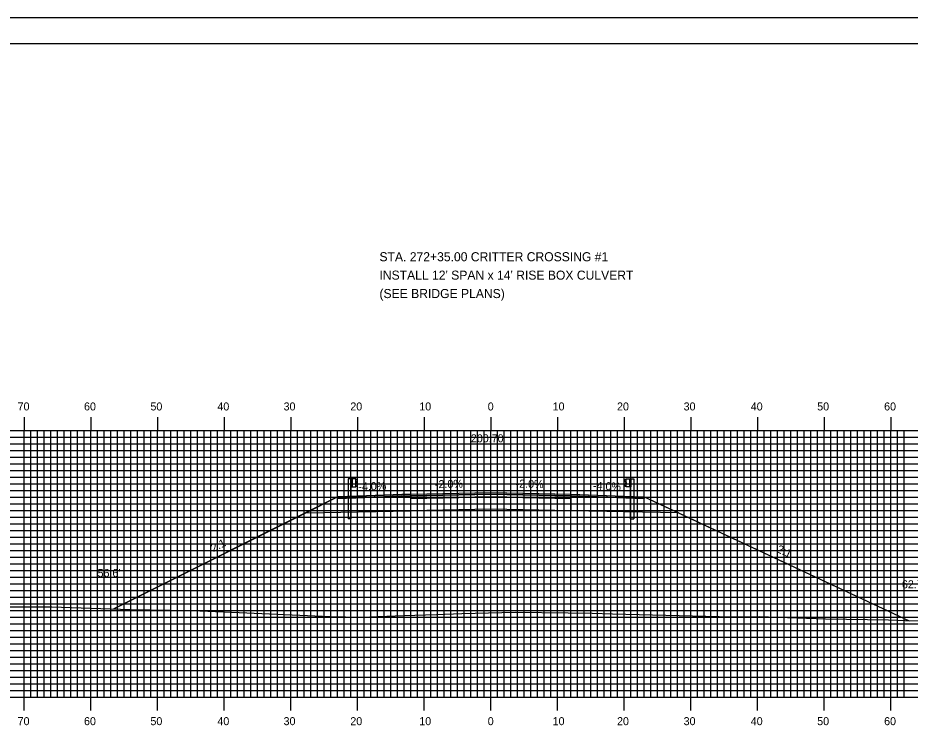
# Model space of a CAD drawing. Extents: x 1808619 to 1808962, y 442591 to 442811.
# Drawn here: x 1808713.9 to 1808847.7, y 442702.5 to 442810.5 of the extents above; entities that cross this region are included whole.
import ezdxf

# ---------------------------------------------------------------- set-up
doc = ezdxf.new("R2010")
doc.units = 0
for name, color, linetype in [('ANNOTATION', 7, 'Continuous'), ('BORDER', 7, 'Continuous'), ('D_Guardrail_Beam_Lt', 7, 'Continuous'), ('D_Guardrail_Beam_Rt', 7, 'Continuous'), ('D_Roadway_Centerline', 7, 'Continuous'), ('D_Roadway_Centerline_Text', 7, 'Continuous'), ('D_Roadway_Edge_Shoulder', 7, 'Continuous'), ('D_Roadway_Edge_TW', 7, 'Continuous'), ('D_Roadway_Pavement', 7, 'Continuous'), ('D_Roadway_SlopeLines', 7, 'Continuous'), ('D_Roadway_SubGrade', 7, 'Continuous'), ('D_Text_Standard', 7, 'Continuous'), ('H_V ANNOTATION', 7, 'Continuous'), ('MAJOR', 7, 'Continuous'), ('MINOR', 7, 'Continuous'), ('PLOT BOUNDARY', 7, 'Continuous'), ('S_Roadway_Centerline', 7, 'Continuous')]:
    doc.layers.add(name, color=color, linetype=linetype)

msp = doc.modelspace()

# ---------------------------------------------------------------- linework, layer by layer
at = {"layer": 'BORDER'}
msp.add_lwpolyline([(1808635.21, 442596.67), (1808955.21, 442596.67), (1808955.21, 442806.67), (1808635.21, 442806.67)], close=True, dxfattribs=at)
at = {"layer": 'D_Guardrail_Beam_Lt'}
for p, q in [((1808763.38, 442741.39), (1808763.38, 442735.39)), ((1808763.85, 442741.39), (1808763.38, 442741.39)), ((1808764.54, 442741.39), (1808763.85, 442741.39)), ((1808763.85, 442741.39), (1808763.85, 442740.23)), ((1808763.92, 442741.39), (1808763.92, 442740.23)), ((1808764.02, 442741.39), (1808764.02, 442740.23)), ((1808764.54, 442740.23), (1808764.54, 442741.39)), ((1808764.54, 442741.31), (1808764.61, 442741.3)), ((1808764.54, 442740.85), (1808764.54, 442740.78)), ((1808764.77, 442741.05), (1808764.58, 442740.91)), ((1808764.58, 442740.71), (1808764.77, 442740.57)), ((1808764.63, 442741.29), (1808764.77, 442741.19)), ((1808764.77, 442740.43), (1808764.63, 442740.33)), ((1808763.85, 442740.23), (1808764.54, 442740.23)), ((1808763.87, 442735.39), (1808763.87, 442740.23)), ((1808764.61, 442740.32), (1808764.54, 442740.31)), ((1808763.87, 442735.39), (1808763.38, 442735.39))]:
    msp.add_line(p, q, dxfattribs=at)
for centre, major_axis, start_param, end_param in [((1808764.62, 442740.85), (-0.0789, 0), 5.323254, 6.283185), ((1808764.62, 442740.78), (-0.0789, 0), 6.283185, 7.243116), ((1808764.61, 442741.25), (0.0417, 0), 0.959931, 1.376053), ((1808764.72, 442741.12), (0.0877, 0), 5.323254, 7.243116), ((1808764.72, 442740.5), (0.0877, 0), 5.323254, 7.243116), ((1808764.61, 442740.37), (0.0417, 0), 4.907132, 5.323254)]:
    msp.add_ellipse(centre, major_axis=major_axis, ratio=0.995501, start_param=start_param, end_param=end_param, dxfattribs=at)
at = {"layer": 'D_Guardrail_Beam_Rt'}
for p, q in [((1808804.99, 442741.29), (1808804.85, 442741.19)), ((1808804.85, 442741.05), (1808805.04, 442740.91)), ((1808805.04, 442740.71), (1808804.85, 442740.57)), ((1808804.85, 442740.43), (1808804.99, 442740.33)), ((1808805.08, 442741.31), (1808805.01, 442741.3)), ((1808805.08, 442741.39), (1808805.77, 442741.39)), ((1808805.08, 442740.23), (1808805.08, 442741.39)), ((1808805.08, 442740.85), (1808805.08, 442740.78)), ((1808805.6, 442741.39), (1808805.6, 442740.23)), ((1808805.71, 442741.39), (1808805.71, 442740.23)), ((1808805.77, 442741.39), (1808806.24, 442741.39)), ((1808805.77, 442741.39), (1808805.77, 442740.23)), ((1808806.24, 442741.39), (1808806.24, 442735.39)), ((1808805.01, 442740.32), (1808805.08, 442740.31)), ((1808805.77, 442740.23), (1808805.08, 442740.23)), ((1808805.75, 442735.39), (1808805.75, 442740.23)), ((1808805.75, 442735.39), (1808806.24, 442735.39))]:
    msp.add_line(p, q, dxfattribs=at)
for centre, major_axis, start_param, end_param in [((1808804.9, 442741.12), (-0.0877, 0), 5.323254, 7.243116), ((1808804.9, 442740.5), (-0.0877, 0), 5.323254, 7.243116), ((1808805.02, 442741.25), (-0.0417, 0), 4.907132, 5.323254), ((1808805, 442740.85), (0.0789, 0), 0, 0.959931), ((1808805, 442740.78), (0.0789, 0), 5.323254, 6.283185), ((1808805.02, 442740.37), (-0.0417, 0), 0.959931, 1.376053)]:
    msp.add_ellipse(centre, major_axis=major_axis, ratio=0.995501, start_param=start_param, end_param=end_param, dxfattribs=at)
at = {"layer": 'D_Roadway_Centerline'}
msp.add_lwpolyline([(1808728.25, 442721.91), (1808757.06, 442736.32), (1808761.81, 442738.69), (1808764.81, 442738.81), (1808772.81, 442739.13), (1808784.81, 442739.37), (1808796.81, 442739.13), (1808804.81, 442738.81), (1808807.81, 442738.69), (1808812.92, 442736.31), (1808847.56, 442720.14)], dxfattribs=at)
at = {"layer": 'D_Roadway_Edge_Shoulder'}
for points in [[(1808772.81, 442739.13), (1808764.81, 442738.81), (1808764.81, 442738.81), (1808761.81, 442738.69), (1808761.81, 442738.44), (1808772.81, 442738.88)], [(1808796.81, 442739.13), (1808804.81, 442738.81), (1808804.81, 442738.81), (1808807.81, 442738.69), (1808807.81, 442738.44), (1808796.81, 442738.88)]]:
    msp.add_lwpolyline(points, close=True, dxfattribs=at)
at = {"layer": 'D_Roadway_Edge_TW'}
msp.add_lwpolyline([(1808772.81, 442738.88), (1808772.81, 442739.13), (1808784.81, 442739.37), (1808796.81, 442739.13), (1808796.81, 442738.88), (1808784.81, 442739.12)], close=True, dxfattribs=at)
at = {"layer": 'D_Roadway_Pavement'}
msp.add_lwpolyline([(1808772.81, 442738.46), (1808772.81, 442738.88), (1808784.81, 442739.12), (1808796.81, 442738.88), (1808796.81, 442738.46), (1808784.81, 442738.7)], close=True, dxfattribs=at)
for points in [[(1808772.81, 442738.88), (1808772.81, 442738.46)], [(1808796.81, 442738.88), (1808796.81, 442738.46)]]:
    msp.add_lwpolyline(points, dxfattribs=at)
at = {"layer": 'D_Roadway_SlopeLines'}
for points in [[(1808761.81, 442738.69), (1808728.25, 442721.91)], [(1808807.81, 442738.69), (1808847.56, 442720.14)]]:
    msp.add_lwpolyline(points, dxfattribs=at)
at = {"layer": 'D_Roadway_SubGrade'}
for points in [[(1808772.81, 442738.46), (1808772.81, 442738.88), (1808761.81, 442738.44), (1808761.81, 442738.69), (1808757.06, 442736.32), (1808772.81, 442736.63)], [(1808772.81, 442736.63), (1808772.81, 442738.88), (1808772.81, 442738.46), (1808784.81, 442738.7), (1808796.81, 442738.46), (1808796.81, 442738.88), (1808796.81, 442736.63), (1808784.81, 442736.87)], [(1808796.81, 442738.46), (1808796.81, 442738.88), (1808807.81, 442738.44), (1808807.81, 442738.69), (1808812.92, 442736.31), (1808796.81, 442736.63)]]:
    msp.add_lwpolyline(points, close=True, dxfattribs=at)
at = {"layer": 'MAJOR'}
for p, q in [((1808714.81, 442750.67), (1808714.81, 442748.67)), ((1808724.81, 442750.67), (1808724.81, 442748.67)), ((1808734.81, 442750.67), (1808734.81, 442748.67)), ((1808744.81, 442750.67), (1808744.81, 442748.67)), ((1808754.81, 442750.67), (1808754.81, 442748.67)), ((1808764.81, 442750.67), (1808764.81, 442748.67)), ((1808774.81, 442750.67), (1808774.81, 442748.67)), ((1808784.81, 442750.67), (1808784.81, 442748.67)), ((1808794.81, 442750.67), (1808794.81, 442748.67)), ((1808804.81, 442750.67), (1808804.81, 442748.67)), ((1808814.81, 442750.67), (1808814.81, 442748.67)), ((1808824.81, 442750.67), (1808824.81, 442748.67)), ((1808834.81, 442750.67), (1808834.81, 442748.67)), ((1808844.81, 442750.67), (1808844.81, 442748.67)), ((1808644.81, 442748.67), (1808924.81, 442748.67)), ((1808644.81, 442748.67), (1808924.81, 442748.67)), ((1808714.81, 442708.67), (1808714.81, 442748.67)), ((1808724.81, 442708.67), (1808724.81, 442748.67)), ((1808734.81, 442708.67), (1808734.81, 442748.67)), ((1808744.81, 442708.67), (1808744.81, 442748.67)), ((1808754.81, 442708.67), (1808754.81, 442748.67)), ((1808764.81, 442708.67), (1808764.81, 442748.67)), ((1808774.81, 442708.67), (1808774.81, 442748.67)), ((1808784.81, 442708.67), (1808784.81, 442748.67)), ((1808794.81, 442708.67), (1808794.81, 442748.67)), ((1808804.81, 442708.67), (1808804.81, 442748.67)), ((1808814.81, 442708.67), (1808814.81, 442748.67)), ((1808824.81, 442708.67), (1808824.81, 442748.67)), ((1808834.81, 442708.67), (1808834.81, 442748.67)), ((1808844.81, 442708.67), (1808844.81, 442748.67)), ((1808644.81, 442743.67), (1808924.81, 442743.67)), ((1808644.81, 442738.67), (1808924.81, 442738.67)), ((1808644.81, 442733.67), (1808924.81, 442733.67)), ((1808644.81, 442728.67), (1808924.81, 442728.67)), ((1808644.81, 442723.67), (1808924.81, 442723.67)), ((1808644.81, 442718.67), (1808924.81, 442718.67)), ((1808644.81, 442713.67), (1808924.81, 442713.67)), ((1808644.81, 442708.67), (1808924.81, 442708.67)), ((1808644.81, 442708.67), (1808924.81, 442708.67)), ((1808714.81, 442706.66), (1808714.81, 442708.67)), ((1808724.81, 442706.66), (1808724.81, 442708.67)), ((1808734.81, 442706.66), (1808734.81, 442708.67)), ((1808744.81, 442706.66), (1808744.81, 442708.67)), ((1808754.81, 442706.66), (1808754.81, 442708.67)), ((1808764.81, 442706.66), (1808764.81, 442708.67)), ((1808774.81, 442706.66), (1808774.81, 442708.67)), ((1808784.81, 442706.66), (1808784.81, 442708.67)), ((1808794.81, 442706.66), (1808794.81, 442708.67)), ((1808804.81, 442706.66), (1808804.81, 442708.67)), ((1808814.81, 442706.66), (1808814.81, 442708.67)), ((1808824.81, 442706.66), (1808824.81, 442708.67)), ((1808834.81, 442706.66), (1808834.81, 442708.67)), ((1808844.81, 442706.66), (1808844.81, 442708.67))]:
    msp.add_line(p, q, dxfattribs=at)
at = {"layer": 'MINOR'}
for p, q in [((1808715.81, 442708.67), (1808715.81, 442748.67)), ((1808716.81, 442708.67), (1808716.81, 442748.67)), ((1808717.81, 442708.67), (1808717.81, 442748.67)), ((1808718.81, 442708.67), (1808718.81, 442748.67)), ((1808719.81, 442708.67), (1808719.81, 442748.67)), ((1808720.81, 442708.67), (1808720.81, 442748.67)), ((1808721.81, 442708.67), (1808721.81, 442748.67)), ((1808722.81, 442708.67), (1808722.81, 442748.67)), ((1808723.81, 442708.67), (1808723.81, 442748.67)), ((1808725.81, 442708.67), (1808725.81, 442748.67)), ((1808726.81, 442708.67), (1808726.81, 442748.67)), ((1808727.81, 442708.67), (1808727.81, 442748.67)), ((1808728.81, 442708.67), (1808728.81, 442748.67)), ((1808729.81, 442708.67), (1808729.81, 442748.67)), ((1808730.81, 442708.67), (1808730.81, 442748.67)), ((1808731.81, 442708.67), (1808731.81, 442748.67)), ((1808732.81, 442708.67), (1808732.81, 442748.67)), ((1808733.81, 442708.67), (1808733.81, 442748.67)), ((1808735.81, 442708.67), (1808735.81, 442748.67)), ((1808736.81, 442708.67), (1808736.81, 442748.67)), ((1808737.81, 442708.67), (1808737.81, 442748.67)), ((1808738.81, 442708.67), (1808738.81, 442748.67)), ((1808739.81, 442708.67), (1808739.81, 442748.67)), ((1808740.81, 442708.67), (1808740.81, 442748.67)), ((1808741.81, 442708.67), (1808741.81, 442748.67)), ((1808742.81, 442708.67), (1808742.81, 442748.67)), ((1808743.81, 442708.67), (1808743.81, 442748.67)), ((1808745.81, 442708.67), (1808745.81, 442748.67)), ((1808746.81, 442708.67), (1808746.81, 442748.67)), ((1808747.81, 442708.67), (1808747.81, 442748.67)), ((1808748.81, 442708.67), (1808748.81, 442748.67)), ((1808749.81, 442708.67), (1808749.81, 442748.67)), ((1808750.81, 442708.67), (1808750.81, 442748.67)), ((1808751.81, 442708.67), (1808751.81, 442748.67)), ((1808752.81, 442708.67), (1808752.81, 442748.67)), ((1808753.81, 442708.67), (1808753.81, 442748.67)), ((1808755.81, 442708.67), (1808755.81, 442748.67)), ((1808756.81, 442708.67), (1808756.81, 442748.67)), ((1808757.81, 442708.67), (1808757.81, 442748.67)), ((1808758.81, 442708.67), (1808758.81, 442748.67)), ((1808759.81, 442708.67), (1808759.81, 442748.67)), ((1808760.81, 442708.67), (1808760.81, 442748.67)), ((1808761.81, 442708.67), (1808761.81, 442748.67)), ((1808762.81, 442708.67), (1808762.81, 442748.67)), ((1808763.81, 442708.67), (1808763.81, 442748.67)), ((1808765.81, 442708.67), (1808765.81, 442748.67)), ((1808766.81, 442708.67), (1808766.81, 442748.67)), ((1808767.81, 442708.67), (1808767.81, 442748.67)), ((1808768.81, 442708.67), (1808768.81, 442748.67)), ((1808769.81, 442708.67), (1808769.81, 442748.67)), ((1808770.81, 442708.67), (1808770.81, 442748.67)), ((1808771.81, 442708.67), (1808771.81, 442748.67)), ((1808772.81, 442708.67), (1808772.81, 442748.67)), ((1808773.81, 442708.67), (1808773.81, 442748.67)), ((1808775.81, 442708.67), (1808775.81, 442748.67)), ((1808776.81, 442708.67), (1808776.81, 442748.67)), ((1808777.81, 442708.67), (1808777.81, 442748.67)), ((1808778.81, 442708.67), (1808778.81, 442748.67)), ((1808779.81, 442708.67), (1808779.81, 442748.67)), ((1808780.81, 442708.67), (1808780.81, 442748.67)), ((1808781.81, 442708.67), (1808781.81, 442748.67)), ((1808782.81, 442708.67), (1808782.81, 442748.67)), ((1808783.81, 442708.67), (1808783.81, 442748.67)), ((1808785.81, 442708.67), (1808785.81, 442748.67)), ((1808786.81, 442708.67), (1808786.81, 442748.67)), ((1808787.81, 442708.67), (1808787.81, 442748.67)), ((1808788.81, 442708.67), (1808788.81, 442748.67)), ((1808789.81, 442708.67), (1808789.81, 442748.67)), ((1808790.81, 442708.67), (1808790.81, 442748.67)), ((1808791.81, 442708.67), (1808791.81, 442748.67)), ((1808792.81, 442708.67), (1808792.81, 442748.67)), ((1808793.81, 442708.67), (1808793.81, 442748.67)), ((1808795.81, 442708.67), (1808795.81, 442748.67)), ((1808796.81, 442708.67), (1808796.81, 442748.67)), ((1808797.81, 442708.67), (1808797.81, 442748.67)), ((1808798.81, 442708.67), (1808798.81, 442748.67)), ((1808799.81, 442708.67), (1808799.81, 442748.67)), ((1808800.81, 442708.67), (1808800.81, 442748.67)), ((1808801.81, 442708.67), (1808801.81, 442748.67)), ((1808802.81, 442708.67), (1808802.81, 442748.67)), ((1808803.81, 442708.67), (1808803.81, 442748.67)), ((1808805.81, 442708.67), (1808805.81, 442748.67)), ((1808806.81, 442708.67), (1808806.81, 442748.67)), ((1808807.81, 442708.67), (1808807.81, 442748.67)), ((1808808.81, 442708.67), (1808808.81, 442748.67)), ((1808809.81, 442708.67), (1808809.81, 442748.67)), ((1808810.81, 442708.67), (1808810.81, 442748.67)), ((1808811.81, 442708.67), (1808811.81, 442748.67)), ((1808812.81, 442708.67), (1808812.81, 442748.67)), ((1808813.81, 442708.67), (1808813.81, 442748.67)), ((1808815.81, 442708.67), (1808815.81, 442748.67)), ((1808816.81, 442708.67), (1808816.81, 442748.67)), ((1808817.81, 442708.67), (1808817.81, 442748.67)), ((1808818.81, 442708.67), (1808818.81, 442748.67)), ((1808819.81, 442708.67), (1808819.81, 442748.67)), ((1808820.81, 442708.67), (1808820.81, 442748.67)), ((1808821.81, 442708.67), (1808821.81, 442748.67)), ((1808822.81, 442708.67), (1808822.81, 442748.67)), ((1808823.81, 442708.67), (1808823.81, 442748.67)), ((1808825.81, 442708.67), (1808825.81, 442748.67)), ((1808826.81, 442708.67), (1808826.81, 442748.67)), ((1808827.81, 442708.67), (1808827.81, 442748.67)), ((1808828.81, 442708.67), (1808828.81, 442748.67)), ((1808829.81, 442708.67), (1808829.81, 442748.67)), ((1808830.81, 442708.67), (1808830.81, 442748.67)), ((1808831.81, 442708.67), (1808831.81, 442748.67)), ((1808832.81, 442708.67), (1808832.81, 442748.67)), ((1808833.81, 442708.67), (1808833.81, 442748.67)), ((1808835.81, 442708.67), (1808835.81, 442748.67)), ((1808836.81, 442708.67), (1808836.81, 442748.67)), ((1808837.81, 442708.67), (1808837.81, 442748.67)), ((1808838.81, 442708.67), (1808838.81, 442748.67)), ((1808839.81, 442708.67), (1808839.81, 442748.67)), ((1808840.81, 442708.67), (1808840.81, 442748.67)), ((1808841.81, 442708.67), (1808841.81, 442748.67)), ((1808842.81, 442708.67), (1808842.81, 442748.67)), ((1808843.81, 442708.67), (1808843.81, 442748.67)), ((1808845.81, 442708.67), (1808845.81, 442748.67)), ((1808846.81, 442708.67), (1808846.81, 442748.67)), ((1808644.81, 442747.67), (1808924.81, 442747.67)), ((1808644.81, 442746.67), (1808924.81, 442746.67)), ((1808644.81, 442745.67), (1808924.81, 442745.67)), ((1808644.81, 442744.67), (1808924.81, 442744.67)), ((1808644.81, 442742.67), (1808924.81, 442742.67)), ((1808644.81, 442741.67), (1808924.81, 442741.67)), ((1808644.81, 442740.67), (1808924.81, 442740.67)), ((1808644.81, 442739.67), (1808924.81, 442739.67)), ((1808644.81, 442737.67), (1808924.81, 442737.67)), ((1808644.81, 442736.67), (1808924.81, 442736.67)), ((1808644.81, 442735.67), (1808924.81, 442735.67)), ((1808644.81, 442734.67), (1808924.81, 442734.67)), ((1808644.81, 442732.67), (1808924.81, 442732.67)), ((1808644.81, 442731.67), (1808924.81, 442731.67)), ((1808644.81, 442730.67), (1808924.81, 442730.67)), ((1808644.81, 442729.67), (1808924.81, 442729.67)), ((1808644.81, 442727.67), (1808924.81, 442727.67)), ((1808644.81, 442726.67), (1808924.81, 442726.67)), ((1808644.81, 442725.67), (1808924.81, 442725.67)), ((1808644.81, 442724.67), (1808924.81, 442724.67)), ((1808644.81, 442722.67), (1808924.81, 442722.67)), ((1808644.81, 442721.67), (1808924.81, 442721.67)), ((1808644.81, 442720.67), (1808924.81, 442720.67)), ((1808644.81, 442719.67), (1808924.81, 442719.67)), ((1808644.81, 442717.67), (1808924.81, 442717.67)), ((1808644.81, 442716.67), (1808924.81, 442716.67)), ((1808644.81, 442715.67), (1808924.81, 442715.67)), ((1808644.81, 442714.67), (1808924.81, 442714.67)), ((1808644.81, 442712.67), (1808924.81, 442712.67)), ((1808644.81, 442711.67), (1808924.81, 442711.67)), ((1808644.81, 442710.67), (1808924.81, 442710.67)), ((1808644.81, 442709.67), (1808924.81, 442709.67))]:
    msp.add_line(p, q, dxfattribs=at)
at = {"layer": 'PLOT BOUNDARY'}
msp.add_lwpolyline([(1808619.02, 442590.55), (1808959.02, 442590.55), (1808959.02, 442810.55), (1808619.02, 442810.55)], close=True, dxfattribs=at)
at = {"layer": 'S_Roadway_Centerline'}
msp.add_lwpolyline([(1808703.3, 442722.21), (1808718.65, 442722.23), (1808718.77, 442722.22), (1808718.93, 442722.22), (1808730.71, 442721.83), (1808739.94, 442721.65), (1808745.89, 442721.41), (1808760.7, 442720.77), (1808765.35, 442720.68), (1808771.74, 442720.94), (1808776.63, 442721.07), (1808780.45, 442721.24), (1808788.43, 442721.41), (1808796.38, 442721.32), (1808799.97, 442721.26), (1808803.02, 442721.17), (1808821.05, 442720.71), (1808825.03, 442720.75), (1808835.01, 442720.4), (1808844.43, 442720.26), (1808846.93, 442720.15), (1808867.17, 442720.02)], dxfattribs=at)

# ---------------------------------------------------------------- texts
at = {"layer": 'ANNOTATION'}
for s, p in [('STA. 272+35.00 CRITTER CROSSING #1', (1808768.09, 442774.04)), ("INSTALL 12' SPAN x 14' RISE BOX CULVERT", (1808768.09, 442771.28)), ('(SEE BRIDGE PLANS)', (1808768.09, 442768.52))]:
    msp.add_text(s, height=1.36, dxfattribs=at).set_placement(p)
for s, rotation, p in [('-4.0%', 2.2906, (1808764.94, 442739.62)), ('-2.0%', 1.1458, (1808776.42, 442740)), ('-2.0%', 358.8542, (1808788.5, 442740.1)), ('-4.0%', 357.7094, (1808800.1, 442739.8)), ('2:1', 26.5651, (1808743.18, 442730.41)), ('2:1', 334.9831, (1808827.56, 442730.48))]:
    msp.add_text(s, height=1.2, rotation=rotation, dxfattribs=at).set_placement(p)
at = {"layer": 'D_Roadway_Centerline'}
for s, p in [('C', (1808784.81, 442739.37)), ('L', (1808784.81, 442739.36))]:
    msp.add_text(s, height=0.0146, dxfattribs=at).set_placement(p)
at = {"layer": 'D_Roadway_Centerline_Text'}
msp.add_text('200.70', height=1.2, dxfattribs=at).set_placement((1808781.8, 442746.89))
at = {"layer": 'D_Text_Standard'}
for s, p in [("56.6'", (1808725.81, 442726.69)), ("62.7'", (1808846.45, 442725))]:
    msp.add_text(s, height=1.2, dxfattribs=at).set_placement(p)
at = {"layer": 'H_V ANNOTATION'}
for s, p in [('70', (1808713.82, 442751.67)), ('60', (1808723.78, 442751.67)), ('50', (1808733.74, 442751.67)), ('40', (1808743.78, 442751.67)), ('30', (1808753.71, 442751.67)), ('20', (1808763.72, 442751.67)), ('10', (1808774.06, 442751.67)), ('0', (1808784.33, 442751.67)), ('10', (1808794.06, 442751.67)), ('20', (1808803.72, 442751.67)), ('30', (1808813.71, 442751.67)), ('40', (1808823.78, 442751.67)), ('50', (1808833.74, 442751.67)), ('60', (1808843.78, 442751.67)), ('70', (1808713.82, 442704.47)), ('60', (1808723.78, 442704.47)), ('50', (1808733.74, 442704.47)), ('40', (1808743.78, 442704.47)), ('30', (1808753.71, 442704.47)), ('20', (1808763.72, 442704.47)), ('10', (1808774.06, 442704.47)), ('0', (1808784.33, 442704.47)), ('10', (1808794.06, 442704.47)), ('20', (1808803.72, 442704.47)), ('30', (1808813.71, 442704.47)), ('40', (1808823.78, 442704.47)), ('50', (1808833.74, 442704.47)), ('60', (1808843.78, 442704.47))]:
    msp.add_text(s, height=1.2, dxfattribs=at).set_placement(p)

doc.saveas('drawing.dxf')
